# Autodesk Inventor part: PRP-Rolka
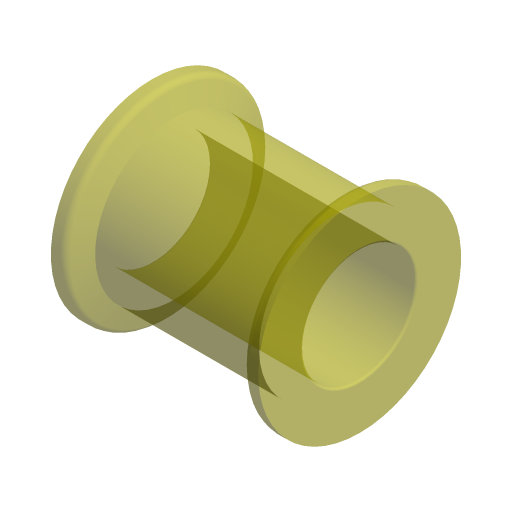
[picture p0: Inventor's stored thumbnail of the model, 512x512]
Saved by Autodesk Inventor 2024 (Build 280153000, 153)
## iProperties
Created: 2023-03
Part Number: PRP-Rolka
Document SubType Name: Modeling
Designer: Andrzej Jaskulski
Material: Kurs-AJ
Density: 1 g/cm^3
Mass: 26.4779 g
Surface Area: 118.848 cm^2
Volume: 26.4779 cm^3
Appearance: Przezroczyste — żółte
Checked By: A.J.
Engr Approved By: Andrzej Jaskulski
Mfg Approved By: Andrzej Jaskulski
Authority: A.J.
Company: ATC
Control State: 0
Master: False
Checked Out: False
Shininess: 20.0
Length Units: 11269
Angle Units: 11279
Time Units: 11290
Mass Units: 11283
Length Display Precision: 3
Angle Display Precision: 2
Compacted: True
Density: 0.0
Volumn: 0.0
Area: 0.0
PropertySet Name: Model Information
Title: A.J.: Kurs R2024-MEP
Author: Andrzej Jaskulski
Revision Number: 1/24
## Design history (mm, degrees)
node "Revolution1" dims "d7" = 90 deg
node "Fillet1" dims "d8" = 1.5
node "Fillet2" dims "d11" = 0.5
node "Bryła1"
node "Korpusy bryłowe"
node "Korpusy powierzchniowe"
sketch "Sketch1"
  geometry: L1 (20, -40)-(66, -40); L2 (66, -40)-(66, -30); L3 (66, -30)-(63, -30); L4 (63, -30)-(61.18, -35); L5 (61.18, -35)-(24.82, -35); L6 (24.82, -35)-(23, -30); L7 (23, -30)-(20, -30); L8 (20, -30)-(20, -40); L9 (14, -52.5)-(73, -52.5)
  constraints: 18 end point, 4 parallel, 3 equal length, 2 perpendicular, 1 horizontal, 1 other
  dimensions: "d0" = 10 distance of L1.end L2.end; "d1" = 5 distance between parallel lines of L1 L5; "d2" = 3 distance of L2.end L3.end; "d4" = 110 deg angle of L5 L4; "d5" = 46 distance of L2.end L7.end (derived); "d6" = 12.5 distance between parallel lines of L9 L1
